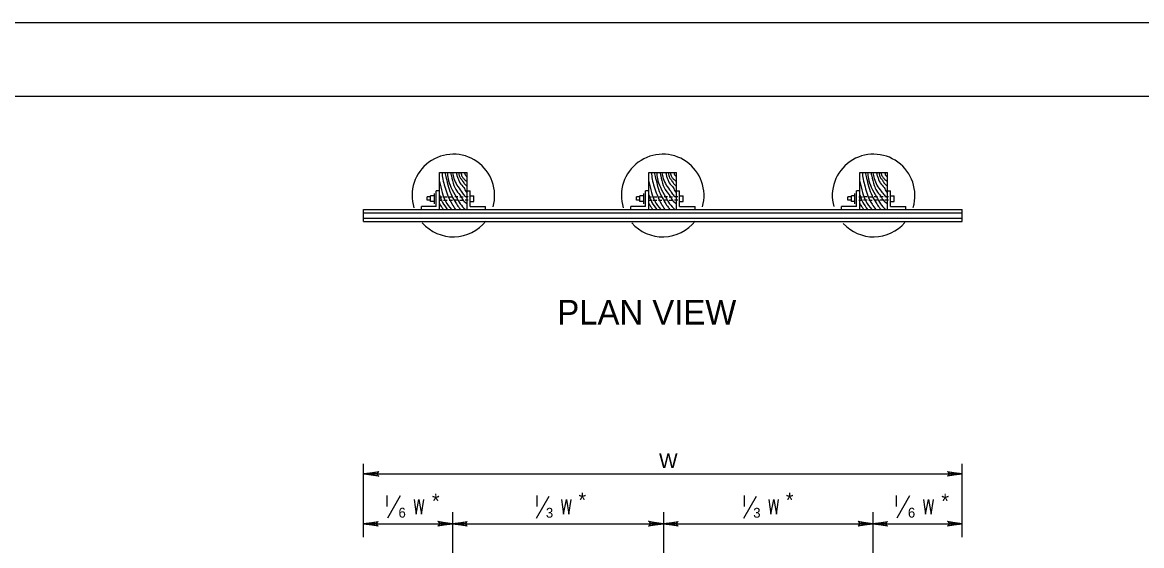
# Model space of a CAD drawing. Extents: x -2340 to 628, y -879 to 309.
# Drawn here: x 130.1 to 357.8, y 203 to 309.4 of the extents above; entities that cross this region are included whole.
import ezdxf

# ---------------------------------------------------------------- set-up
doc = ezdxf.new("R2010")
doc.units = 0
for name, color, linetype in [('Level 1', 7, 'Continuous'), ('Level 2', 7, 'Continuous'), ('Level 3', 7, 'Continuous'), ('PLT-BNDY', 7, 'Continuous')]:
    doc.layers.add(name, color=color, linetype=linetype)

# ---------------------------------------------------------------- blocks, each defined once
blk = doc.blocks.new('RARROW')
at = {"layer": 'Level 3'}
blk.add_lwpolyline([(-0.0576, 0.0072), (-0.0555, 0.0031), (0, 0), (-0.0576, 0.0072), (-0.0606, 0.0098), (0, 0), (-0.0555, -0.0027), (-0.0575, -0.0069), (0, 0), (-0.0606, -0.0096), (-0.0575, -0.0069)], dxfattribs=at)

msp = doc.modelspace()

# ---------------------------------------------------------------- linework, layer by layer
at = {"layer": 'Level 1'}
msp.add_line((-236.39, 294.44), (549.61, 294.44), dxfattribs=at)
at = {"layer": 'Level 2'}
for p, q in [((214.97, 278.88), (220.6, 278.88)), ((257.58, 278.88), (263.2, 278.88)), ((300.5, 278.88), (306.12, 278.88)), ((214.97, 275.13), (214.3, 275.13)), ((220.6, 275.13), (221.2, 275.13)), ((257.58, 275.13), (256.9, 275.13)), ((263.2, 275.13), (263.8, 275.13)), ((300.5, 275.13), (299.82, 275.13)), ((306.12, 275.13), (306.72, 275.13)), ((199.49, 271.38), (321.32, 271.38)), ((214.3, 271.98), (211.3, 271.98)), ((221.2, 271.98), (224.35, 271.98)), ((256.9, 271.98), (253.9, 271.98)), ((263.8, 271.98), (266.95, 271.98)), ((299.82, 271.98), (296.75, 271.98)), ((306.72, 271.98), (309.87, 271.98)), ((199.49, 270.71), (321.32, 270.71)), ((199.49, 269.58), (321.32, 269.58)), ((199.49, 268.91), (321.32, 268.91))]:
    msp.add_line(p, q, dxfattribs=at)
at = {"layer": 'Level 3'}
for p, q in [((214.97, 271.38), (214.97, 278.88)), ((220.6, 271.38), (220.6, 278.88)), ((257.58, 271.38), (257.58, 278.88)), ((263.2, 271.38), (263.2, 278.88)), ((300.5, 271.38), (300.5, 278.88)), ((306.12, 271.38), (306.12, 278.88)), ((212.42, 273.26), (212.42, 273.93)), ((213.1, 273.93), (212.42, 273.93)), ((213.1, 272.96), (213.1, 274.16)), ((213.92, 274.16), (213.1, 274.16)), ((213.92, 272.51), (213.92, 274.61)), ((214.3, 271.98), (214.3, 275.13)), ((214.82, 273.93), (215.5, 273.93)), ((215.8, 273.93), (216.55, 273.93)), ((216.92, 273.93), (217.6, 273.93)), ((218.72, 273.93), (218.05, 273.93)), ((219.1, 273.93), (219.77, 273.93)), ((220.82, 273.93), (220.15, 273.93)), ((221.2, 271.98), (221.2, 275.13)), ((221.2, 274.16), (221.95, 274.16)), ((221.95, 272.96), (221.95, 274.16)), ((255.03, 273.26), (255.03, 273.93)), ((255.7, 273.93), (255.03, 273.93)), ((255.7, 272.96), (255.7, 274.16)), ((256.53, 274.16), (255.7, 274.16)), ((256.53, 272.51), (256.53, 274.61)), ((256.9, 271.98), (256.9, 275.13)), ((257.43, 273.93), (258.1, 273.93)), ((258.4, 273.93), (259.15, 273.93)), ((259.53, 273.93), (260.2, 273.93)), ((261.33, 273.93), (260.65, 273.93)), ((261.7, 273.93), (262.38, 273.93)), ((263.43, 273.93), (262.75, 273.93)), ((263.8, 271.98), (263.8, 275.13)), ((263.8, 274.16), (264.55, 274.16)), ((264.55, 272.96), (264.55, 274.16)), ((298.02, 273.26), (298.02, 273.93)), ((298.77, 273.93), (298.02, 273.93)), ((298.77, 272.96), (298.77, 274.16)), ((299.45, 274.16), (298.77, 274.16)), ((299.45, 272.51), (299.45, 274.61)), ((299.82, 271.98), (299.82, 275.13)), ((300.27, 273.93), (301.02, 273.93)), ((302, 273.93), (301.25, 273.93)), ((302.3, 273.93), (302.97, 273.93)), ((304.1, 273.93), (303.42, 273.93)), ((305.22, 273.93), (304.55, 273.93)), ((306.35, 273.93), (305.6, 273.93)), ((306.72, 271.98), (306.72, 275.13)), ((306.72, 274.16), (307.47, 274.16)), ((307.47, 272.96), (307.47, 274.16)), ((199.49, 268.91), (199.49, 271.38)), ((211.3, 271.38), (211.3, 271.98)), ((213.1, 273.26), (212.42, 273.26)), ((213.92, 272.96), (213.1, 272.96)), ((214.82, 273.26), (215.5, 273.26)), ((215.8, 273.26), (216.55, 273.26)), ((216.92, 273.26), (217.6, 273.26)), ((218.72, 273.26), (218.05, 273.26)), ((219.1, 273.26), (219.77, 273.26)), ((220.82, 273.26), (220.15, 273.26)), ((221.2, 272.96), (221.95, 272.96)), ((224.35, 271.38), (224.35, 271.98)), ((253.9, 271.38), (253.9, 271.98)), ((255.7, 273.26), (255.03, 273.26)), ((256.53, 272.96), (255.7, 272.96)), ((257.43, 273.26), (258.1, 273.26)), ((258.4, 273.26), (259.15, 273.26)), ((259.53, 273.26), (260.2, 273.26)), ((261.33, 273.26), (260.65, 273.26)), ((261.7, 273.26), (262.38, 273.26)), ((263.43, 273.26), (262.75, 273.26)), ((263.8, 272.96), (264.55, 272.96)), ((266.95, 271.38), (266.95, 271.98)), ((296.75, 271.38), (296.75, 271.98)), ((298.77, 273.26), (298.02, 273.26)), ((299.45, 272.96), (298.77, 272.96)), ((300.27, 273.26), (301.02, 273.26)), ((302, 273.26), (301.25, 273.26)), ((302.3, 273.26), (302.97, 273.26)), ((304.1, 273.26), (303.42, 273.26)), ((305.22, 273.26), (304.55, 273.26)), ((306.35, 273.26), (305.6, 273.26)), ((306.72, 272.96), (307.47, 272.96)), ((309.87, 271.38), (309.87, 271.98)), ((321.32, 268.91), (321.32, 271.38)), ((199.49, 204.65), (199.49, 219.61)), ((321.32, 204.65), (321.32, 219.61)), ((199.65, 217.56), (321.32, 217.56)), ((217.61, 209.77), (217.61, 193.7)), ((260.53, 209.77), (260.53, 193.7)), ((303.13, 209.77), (303.13, 193.7)), ((199.49, 207.4), (217.61, 207.4)), ((217.61, 207.4), (260.53, 207.4)), ((260.53, 207.4), (303.13, 207.4)), ((303.13, 207.4), (321.32, 207.4))]:
    msp.add_line(p, q, dxfattribs=at)
for points in [[(319.51, 217.8), (319.51, 217.64), (321.32, 217.56), (319.51, 217.8), (319.43, 217.8), (321.32, 217.56), (319.51, 217.48), (319.51, 217.33), (321.32, 217.56), (319.43, 217.33), (319.51, 217.33)], [(204.33, 210.89), (204.33, 213.13)], [(204.45, 208.62), (207, 213.13)], [(209.79, 212.37), (210.21, 209.37), (210.78, 212.37), (211.32, 209.37), (211.8, 212.37)], [(234.71, 208.54), (237.26, 213.05)], [(234.81, 210.92), (234.81, 213.16)], [(239.78, 212.35), (240.2, 209.35), (240.77, 212.35), (241.31, 209.35), (241.78, 212.35)], [(276.9, 208.54), (279.45, 213.05)], [(277, 210.92), (277, 213.16)], [(281.97, 212.35), (282.39, 209.35), (282.96, 212.35), (283.5, 209.35), (283.97, 212.35)], [(307.98, 210.89), (307.98, 213.13)], [(308.1, 208.62), (310.65, 213.13)], [(313.44, 212.37), (313.86, 209.37), (314.43, 212.37), (314.97, 209.37), (315.45, 212.37)]]:
    msp.add_lwpolyline(points, dxfattribs=at)
for centre, start, end in [((217.78, 274.2), 344.085, 197.2873), ((260.38, 274.2), 344.085, 197.2873), ((303.29, 274.2), 343.3743, 195.5154), ((217.78, 274.2), 221.3222, 321.6878), ((260.38, 274.2), 221.3222, 321.6878), ((303.29, 274.2), 222.6593, 319.137)]:
    msp.add_arc(centre, 8.41, start, end, dxfattribs=at)
for points in [[(215.42, 278.88), (215.65, 277.53), (216.02, 275.96), (216.62, 274.31), (217.52, 272.43), (218.2, 271.38)], [(216.02, 278.88), (216.32, 277.76), (217.45, 274.16), (218.27, 272.73), (218.87, 271.83), (219.25, 271.38)], [(216.55, 278.81), (216.7, 277.68), (217.3, 275.88), (218.35, 273.93), (219.17, 272.51), (220.22, 271.38)], [(217.22, 278.88), (217.37, 278.21), (217.9, 276.26), (218.42, 275.21), (219.32, 274.01), (219.85, 273.11), (220.52, 272.58)], [(217.6, 278.81), (217.9, 277.68), (218.5, 276.33), (219.4, 275.06), (219.92, 274.31), (220.52, 273.78)], [(218.42, 278.81), (218.57, 278.06), (218.8, 277.46), (219.1, 276.78), (219.92, 275.81), (220.37, 274.98), (220.52, 274.83)], [(218.87, 278.81), (219.17, 277.83), (219.55, 277.31), (220, 276.63), (220.52, 276.11)], [(219.32, 278.81), (219.55, 278.06), (219.92, 277.61), (220.52, 277.08)], [(220.07, 278.81), (220.15, 278.43), (220.3, 278.28), (220.52, 278.06)], [(258.03, 278.88), (258.25, 277.53), (258.63, 275.96), (259.23, 274.31), (260.13, 272.43), (260.8, 271.38)], [(258.63, 278.88), (258.93, 277.76), (260.05, 274.16), (260.88, 272.73), (261.48, 271.83), (261.85, 271.38)], [(259.15, 278.81), (259.3, 277.68), (259.9, 275.88), (260.95, 273.93), (261.78, 272.51), (262.83, 271.38)], [(259.83, 278.88), (259.98, 278.21), (260.5, 276.26), (261.03, 275.21), (261.93, 274.01), (262.45, 273.11), (263.13, 272.58)], [(260.2, 278.81), (260.5, 277.68), (261.1, 276.33), (262, 275.06), (262.53, 274.31), (263.13, 273.78)], [(261.03, 278.81), (261.18, 278.06), (261.4, 277.46), (261.7, 276.78), (262.53, 275.81), (262.98, 274.98), (263.13, 274.83)], [(261.48, 278.81), (261.78, 277.83), (262.15, 277.31), (262.6, 276.63), (263.13, 276.11)], [(261.93, 278.81), (262.15, 278.06), (262.53, 277.61), (263.13, 277.08)], [(262.68, 278.81), (262.75, 278.43), (262.9, 278.28), (263.13, 278.06)], [(300.95, 278.88), (301.17, 277.53), (301.55, 275.96), (302.07, 274.31), (302.97, 272.43), (303.72, 271.38)], [(301.55, 278.88), (301.85, 277.76), (302.97, 274.16), (303.8, 272.73), (304.4, 271.83), (304.77, 271.38)], [(302.07, 278.81), (302.22, 277.68), (302.82, 275.88), (303.87, 273.93), (304.7, 272.51), (305.67, 271.38)], [(302.75, 278.88), (302.9, 278.21), (303.42, 276.26), (303.87, 275.21), (304.77, 274.01), (305.37, 273.11), (306.05, 272.58)], [(303.12, 278.81), (303.42, 277.68), (303.95, 276.33), (304.85, 275.06), (305.45, 274.31), (306.05, 273.78)], [(303.87, 278.81), (304.1, 278.06), (304.32, 277.46), (304.62, 276.78), (305.45, 275.81), (305.9, 274.98), (306.05, 274.83)], [(304.4, 278.81), (304.7, 277.83), (305.07, 277.31), (305.52, 276.63), (306.05, 276.11)], [(304.77, 278.81), (305.07, 278.06), (305.45, 277.61), (306.05, 277.08)], [(305.6, 278.81), (305.67, 278.43), (305.75, 278.28), (306.05, 278.06)], [(214.97, 277.08), (215.5, 274.83), (216.17, 273.03), (217.37, 271.38)], [(257.58, 277.08), (258.1, 274.83), (258.78, 273.03), (259.98, 271.38)], [(300.5, 277.08), (301.02, 274.83), (301.7, 273.03), (302.9, 271.38)], [(214.97, 274.31), (215.57, 272.81), (216.55, 271.38)], [(257.58, 274.31), (258.18, 272.81), (259.15, 271.38)], [(300.5, 274.31), (301.1, 272.81), (302.07, 271.38)], [(214.97, 272.51), (215.42, 271.83), (215.8, 271.31)], [(257.58, 272.51), (258.03, 271.83), (258.4, 271.31)], [(300.5, 272.51), (300.95, 271.83), (301.32, 271.31)]]:
    msp.add_spline(points, degree=3, dxfattribs=at)
at = {"layer": 'PLT-BNDY'}
msp.add_lwpolyline([(-276.39, 309.44), (564.61, 309.44), (564.61, -284.56), (-276.39, -284.56)], close=True, dxfattribs=at)

# ---------------------------------------------------------------- block references
at = {"layer": 'Level 2', "xscale": 49.50530586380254, "yscale": 51.54709073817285, "rotation": 180}
for p in [(199.65, 217.56), (199.49, 207.4), (217.61, 207.4), (260.52, 207.4), (303.13, 207.4)]:
    msp.add_blockref('RARROW', p, dxfattribs=at)
at = {"layer": 'Level 2', "xscale": 49.50530586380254, "yscale": 51.54709073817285}
for p in [(321.32, 217.56), (217.61, 207.4), (260.52, 207.4), (303.13, 207.4), (321.32, 207.4)]:
    msp.add_blockref('RARROW', p, dxfattribs=at)

# ---------------------------------------------------------------- texts
at = {"layer": 'Level 2'}
for p in [(213.42, 210.53), (243.24, 210.73), (285.43, 210.73), (317.07, 210.53)]:
    msp.add_text('*', height=3, dxfattribs=at).set_placement(p)
at = {"layer": 'Level 3'}
for s, height, p in [('PLAN VIEW', 5, (238.94, 247.95)), ('W', 3, (259.63, 218.74)), ('6', 2, (206.62, 208.66)), ('3', 2, (236.61, 208.64)), ('3', 2, (278.8, 208.64)), ('6', 2, (310.27, 208.66))]:
    msp.add_text(s, height=height, dxfattribs=at).set_placement(p)

doc.saveas('drawing.dxf')
